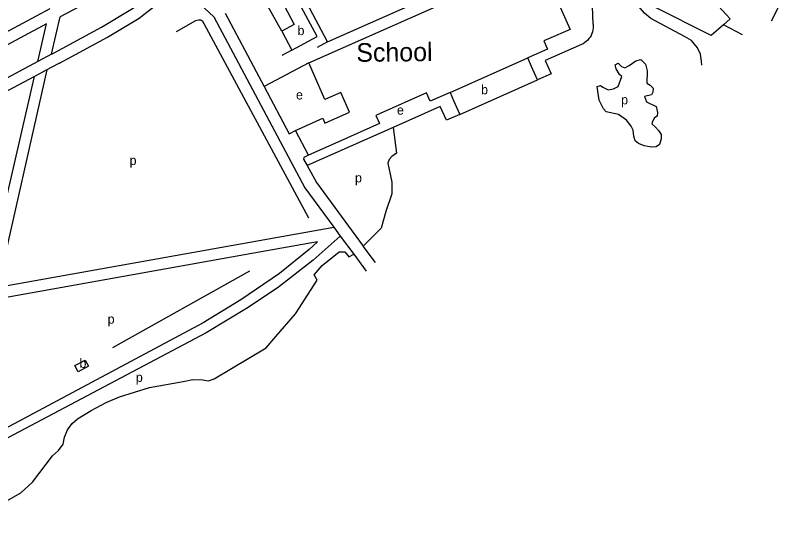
# Model space of a CAD drawing. Extents: x 159261 to 160849, y 382514 to 384534.
# Drawn here: x 160007.7 to 160342.1, y 382659.6 to 382879.4 of the extents above; entities that cross this region are included whole.
import ezdxf

# ---------------------------------------------------------------- set-up
doc = ezdxf.new("R2010")
doc.units = 0
for name, color, linetype in [('BLT_Basislijn', 7, 'Continuous'), ('BLT_Bebouwing', 7, 'Continuous'), ('BLT_Bebouwing_beschrifting', 7, 'Continuous'), ('BLT_Centroide', 7, 'Continuous'), ('BLT_Onderdoorgang_en_onderverdeling', 7, 'Continuous')]:
    doc.layers.add(name, color=color, linetype=linetype)

msp = doc.modelspace()

# ---------------------------------------------------------------- linework, layer by layer
at = {"layer": 'BLT_Basislijn'}
for p, q in [((160121.97, 382872.68), (160106.83, 382900.55)), ((160342.06, 382896.78), (160332.09, 382876.95)), ((160255.69, 382875.77), (160255.02, 382894.36)), ((160141.58, 382868.05), (160189.52, 382889.34)), ((160306.3, 382870.77), (160281.31, 382883.48)), ((160023.17, 382862.83), (160026.87, 382878.91)), ((160017.32, 382859.71), (160021.02, 382875.78)), ((160311.61, 382875.48), (160306.3, 382870.77)), ((160319.83, 382871.1), (160311.61, 382875.48)), ((160141.58, 382868.05), (160137.16, 382865.7)), ((160023.17, 382862.83), (160017.32, 382859.71)), ((160126.34, 382864.55), (160122.05, 382862.22)), ((160017.32, 382859.71), (159983.24, 382841.55)), ((160133.59, 382859.03), (160114.46, 382848.86)), ((160015.85, 382853.26), (159986.11, 382837.42)), ((160169.76, 382831.37), (160132.88, 382815.06)), ((160144.29, 382788.53), (160147.07, 382784.71)), ((160147.07, 382784.71), (160153, 382776.99)), ((160162.22, 382773.34), (160156.96, 382780.42)), ((160153, 382776.99), (160158.26, 382769.65)), ((160049.46, 382736.79), (160108.35, 382769.73))]:
    msp.add_line(p, q, dxfattribs=at)
for points in [[(160063.31, 382903.26), (160054.68, 382896.14), (160046.93, 382889.77), (160042.36, 382887.19), (160026.87, 382878.91)], [(160141.58, 382868.05), (160123.95, 382901.74), (160135.95, 382899.47)], [(160302.31, 382858.15), (160302.24, 382859.83), (160301.78, 382862.78), (160300.52, 382865.51), (160297.82, 382868.68), (160294.89, 382870.43), (160280.49, 382878.14), (160277.65, 382880.47), (160275.11, 382883.5), (160273.25, 382886.8), (160268.8, 382896.54), (160255.93, 382894.51)], [(160023.17, 382862.83), (160024.26, 382863.41), (160044.67, 382874.42), (160057.87, 382882.46), (160069.76, 382891.88), (160074.27, 382894.7)], [(160026.63, 382859), (160047.16, 382870.08), (160060.73, 382878.35), (160072.65, 382887.79), (160079.04, 382891.79)], [(160079.04, 382891.79), (160092.83, 382878.92), (160131.87, 382805.42), (160144.29, 382788.53)], [(160311.61, 382875.48), (160314.51, 382878.05), (160307.86, 382885.13)], [(160022.51, 382882.25), (159946.06, 382841.36)], [(160097.71, 382880.39), (160112.11, 382853.28)], [(160133.65, 382792.39), (160088.66, 382875.9), (160088.14, 382876.87), (160087.3, 382877.37), (160086.22, 382877.48), (160085.02, 382877.14), (160076.68, 382872.43)], [(160021.02, 382875.78), (159948.41, 382836.95)], [(160255.69, 382875.77), (160255.74, 382874.93), (160255.7, 382874.1), (160255.59, 382873.27), (160255.39, 382872.46), (160255.12, 382871.66), (160254.78, 382870.9), (160254.36, 382870.18), (160253.88, 382869.5), (160253.34, 382868.86), (160252.73, 382868.29), (160252.08, 382867.77), (160251.37, 382867.32), (160250.69, 382866.96)], [(160250.69, 382866.96), (160235.07, 382860.08), (160237.62, 382854.33), (160231.77, 382851.77)], [(160021.17, 382856.09), (160000.04, 382762.82), (160136.27, 382787.12), (160144.29, 382788.53)], [(160021.17, 382856.09), (160015.85, 382853.26)], [(160026.63, 382859), (160022.96, 382857.05), (160021.17, 382856.09)], [(159922.81, 382748.95), (159994.67, 382761.8), (160015.85, 382853.26)], [(160112.11, 382853.28), (160114.46, 382848.86)], [(160114.46, 382848.86), (160125.2, 382828.63), (160127.88, 382830.05)], [(160198.44, 382836.93), (160192.72, 382834.45), (160190.04, 382840.36), (160169.76, 382831.37)], [(160169.76, 382831.37), (160171.23, 382820.28)], [(160133.52, 382819.45), (160131.47, 382818.49), (160131.4, 382817.74), (160132.88, 382815.06)], [(160171.23, 382820.28), (160170.27, 382819.65), (160169.21, 382818.82), (160168.1, 382817.64), (160167.59, 382815.96), (160169.25, 382807.87), (160169.25, 382802.89), (160166.62, 382795.28), (160164.62, 382788.16), (160156.96, 382780.42)], [(160132.88, 382815.06), (160136.96, 382807.72), (160156.96, 382780.42)], [(160147.07, 382784.71), (160135.53, 382774.33), (160120.58, 382762.72), (160107.64, 382753.98), (160089.51, 382743.1), (160004.35, 382698.05), (159982.83, 382686.57)], [(160137.38, 382782.24), (160133.79, 382778.97), (160121.06, 382768.61), (160104.37, 382757.24), (160088.2, 382747.38), (159983.99, 382691.71)], [(160137.38, 382782.24), (160115.57, 382778.37), (159998.83, 382757.49)], [(160093.02, 382723.34), (160115.35, 382736.74), (160119.4, 382741.57), (160127.87, 382751.36), (160137.2, 382765.81), (160135.9, 382768.11), (160139.38, 382772.01), (160146.71, 382777.9), (160149.12, 382777.96), (160150.75, 382775.83), (160153, 382776.99)], [(160034.33, 382706.19), (160040.22, 382709.85), (160046.62, 382713.22), (160052.35, 382715.7), (160065.28, 382719.72), (160079.68, 382722.3), (160083.87, 382723.11), (160088.12, 382722.91), (160090.49, 382722.5), (160093.02, 382723.34)], [(159976.73, 382659.56), (159981.34, 382663.01), (159998.86, 382669.41), (160003.77, 382670.78), (160010.07, 382674.4), (160015.04, 382678.99), (160023.54, 382690.37), (160026.11, 382692.55), (160028.19, 382695.38), (160028.77, 382698.35), (160030.07, 382701.51), (160032.1, 382704.13), (160034.33, 382706.19)]]:
    msp.add_lwpolyline(points, dxfattribs=at)
msp.add_lwpolyline([(160257.41, 382848.97), (160258.78, 382849.38), (160259.81, 382848.62), (160262.14, 382847.53), (160264.41, 382847.87), (160266.4, 382848.97), (160268.04, 382853.29), (160267.01, 382854.11), (160265.61, 382856.51), (160265.09, 382858.3), (160266.4, 382858.91), (160267.84, 382857.47), (160269.21, 382856.92), (160271.06, 382858.02), (160273.94, 382859.94), (160276.14, 382860.49), (160278.12, 382858.57), (160278.81, 382855.69), (160278.71, 382850.37), (160280.18, 382849.48), (160281.49, 382848.18), (160281.28, 382846.5), (160280.66, 382845.37), (160277.71, 382844.68), (160278.61, 382842.35), (160282.65, 382840.29), (160283.34, 382837.82), (160283.2, 382836.24), (160282.03, 382835.49), (160281.07, 382833.84), (160280.87, 382832.95), (160282.38, 382831.51), (160283.68, 382830.07), (160284.85, 382828.36), (160284.85, 382826.44), (160284.09, 382823.97), (160282.65, 382823.08), (160280.73, 382822.87), (160277.51, 382823.42), (160275.18, 382824.45), (160273.74, 382825.61), (160273.12, 382827.6), (160272.77, 382830.14), (160272.02, 382831.86), (160270.03, 382834.49), (160266.6, 382836.9), (160261.25, 382837.99), (160260.09, 382839.36), (160258.3, 382843.07)], close=True, dxfattribs=at)
at = {"layer": 'BLT_Bebouwing'}
for p, q in [((160121.97, 382872.68), (160126.34, 382864.55)), ((160236.08, 382865.02), (160227.57, 382861.23)), ((160229.23, 382857.5), (160227.57, 382861.23)), ((160194.23, 382846.42), (160185.72, 382842.64)), ((160194.23, 382846.42), (160195.79, 382842.9)), ((160133.52, 382819.45), (160127.88, 382830.05)), ((160146.09, 382825.04), (160133.52, 382819.45))]:
    msp.add_line(p, q, dxfattribs=at)
for points in [[(160133.59, 382859.03), (160206.77, 382891.53)], [(160126.34, 382864.55), (160137.23, 382870.42), (160128.41, 382886.7), (160123, 382883.74), (160127.39, 382875.62), (160121.97, 382872.68)], [(160239.65, 382887.3), (160245.81, 382873.47)], [(160245.81, 382873.47), (160236.45, 382869.35), (160234.54, 382868.5), (160236.08, 382865.02)], [(160147.3, 382846.31), (160140.56, 382843.31), (160133.59, 382859.03)], [(160231.77, 382851.77), (160229.23, 382857.5)], [(160198.44, 382836.93), (160231.77, 382851.77)], [(160139.61, 382835.27), (160140.52, 382833.22), (160151.05, 382837.9), (160147.3, 382846.31)], [(160185.72, 382842.64), (160184.16, 382846.14), (160164.23, 382837.29), (160162.41, 382836.48), (160163.96, 382833), (160146.09, 382825.04)], [(160195.79, 382842.9), (160198.44, 382836.93)], [(160127.88, 382830.05), (160139.61, 382835.27)]]:
    msp.add_lwpolyline(points, dxfattribs=at)
msp.add_lwpolyline([(160034.62, 382726.43), (160033.22, 382729.08), (160037.63, 382731.4), (160039.02, 382728.75)], close=True, dxfattribs=at)
at = {"layer": 'BLT_Onderdoorgang_en_onderverdeling'}
msp.add_line((160194.23, 382846.42), (160227.57, 382861.23), dxfattribs=at)

# ---------------------------------------------------------------- texts
at = {"layer": 'BLT_Bebouwing_beschrifting'}
msp.add_text('School', height=8, rotation=0.5505, dxfattribs=at).set_placement((160154.05, 382859.52))
at = {"layer": 'BLT_Centroide'}
for s, p in [('b', (160128.77, 382871.02)), ('b', (160207.57, 382845.59)), ('e', (160128.12, 382843.37)), ('p', (160267.68, 382841.26)), ('e', (160171.44, 382836.84)), ('p', (160056.68, 382815.23)), ('p', (160153.43, 382807.74)), ('p', (160047.26, 382747.07)), ('b', (160035.17, 382728.11)), ('p', (160059.38, 382722.06))]:
    msp.add_text(s, height=4, dxfattribs=at).set_placement(p)

doc.saveas('drawing.dxf')
